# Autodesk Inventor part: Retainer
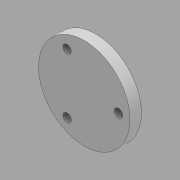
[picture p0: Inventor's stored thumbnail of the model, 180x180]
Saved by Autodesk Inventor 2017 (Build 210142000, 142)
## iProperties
Created: 2016-05
Part Number: Retainer
Material: Generic
Document SubType Name: Modeling
Designer: CADCIM
Density: 1 g/cm^3
Appearance: Default
Author: CADCIM
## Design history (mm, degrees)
sketch "Sketch1"
  geometry: C1 r 100 at (0, 0); 1 further point
  constraints: 1 centre point, 1 coincident
  dimensions: "d0" = 200 diameter of C1
extrude "Extrusion1" new body sketch "Sketch1" distance "d1" = 25; taper "d2" = 0 deg
sketch "Sketch2"
  geometry: 1 further point
sketch "Sketch3" dims "d3" = 150
  geometry: L1 (0, 0)-(102.916, 0); 2 further points
  constraints: 2 end point, 1 coincident, 1 horizontal, 1 horizontal alignment, 1 point on line, 2 other
hole "Hole1" sketch "Sketch3" at (75, 0) diameter "d4" = 18.376; stored, may be unused: countersink angle "d8" = 90 deg, drill point angle "d10" = 118 deg; dims "d5" = 40, "d6" = 4, "d7" = 2, "d9" = 47.3
pattern_circular "Circular Pattern1" dims angle "d12" = 360 deg
body "Solid1"
